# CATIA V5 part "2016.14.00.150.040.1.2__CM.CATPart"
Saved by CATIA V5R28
Part number: 2016.14.00.150.040.1.2__CM
Property "id_number": "2016.14.00.150.040.1.2"
Publications: "Absolute Axis System", "driver", "slider", "base", "cam diagram"
Bounding box of the stored display mesh (mm): x -40 to 190, y -130 to 130, z 0 to 260
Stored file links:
  N:\B2\Normteile\K\2016\11-14\015\cm\2016.14.00.150.040.1.2__CM.CATPart
  H:\CAD_Startmodelle\Tests\fill-in_PRT-SL_TEMPLATE.xlsx
  H:\CAD_Startmodelle\V5-R24\R24_TEMPLATE_PRT_FIBRO_CAM_TECNOLOGIES_INDEX.xlsx
  H:\z_Einordnen\170511__Anfrage_TK_HN\170511__CC01_TKHN.CATPart
  N:\B2\Normteile\K\2016\9xxx\2016.9024.1705.001\Entwurf_\170511__CC01_TKHN.CATPart
  N:\B2\Normteile\K\2016\9xxx\2016.9024.1707.006\Konstruktion\2016.9024.1707.006__HP__CUSTOMIZED_CAM_CM.CATPart
  N:\B2\Normteile\K\2016\9xxx\2016.9024.1707.005\Konstruktion\2016.9024.1707.005__HP__CUSTOMIZED_CAM_CM.CATPart
  N:\B2\Normteile\K\2016\9xxx\2016.9024.1707.008\Konstruktion\2016.9024.1707.008__HP__CUSTOMIZED_CAM_CM.CATPart
  N:\B2\Normteile\K\2016\9xxx\2016.9024.1707.009\Konstruktion\2016.9024.1707.009__HP__CUSTOMIZED_CAM_CM.CATPart
  N:\B2\Normteile\K\2016\9xxx\2016.9024.1707.010\Konstruktion\2016.9024.1707.010__HP__CUSTOMIZED_CAM_CM.CATPart
  N:\B2\Normteile\K\2016\9xxx\2016.9024.1708.002\Konstruktion\2016.9024.1708.002__HP__CUSTOMIZED_CAM_CM.CATPart
  N:\B2\Normteile\K\2016\9xxx\2016.9024.1802.001\Konstruktion\2016.9024.1802.001__HP__CUSTOMIZED_CAM_CM.CATPart
  N:\B2\Normteile\K\2016\9xxx\2016.9024.1802.002\Konstruktion\2016.9024.1802.002__HP__CUSTOMIZED_CAM_CM.CATPart
  N:\B2\Normteile\K\2016\9xxx\2016.9024.1811.003\Konstruktion\2016.9024.1811.003__HP__CUSTOMIZED_CAM_CM.CATPart
  N:\B2\Normteile\K\2016\9xxx\2016.9015.1811.001\Konstruktion\am\2016.9015.1811.001__AM__FCC_HV_DMC_0125-00.CATPart
  N:\B2\Normteile\K\2016\9xxx\2016.9024.1811.009\Konstruktion\2016.9024.1811.009__HP__CUSTOMIZED_CAM_CM.CATPart
  N:\B2\Normteile\K\2016\9xxx\2016.9024.1911.002\Konstruktion\am\2016.9024.1911.002__AM__CUSTOMIZED_CAM_CM.CATPart
  N:\B2\Normteile\K\2016\9xxx\2016.9024.2002.006\Konstruktion\2016.9024.2002.006__AM.CATPart
  N:\B2\Normteile\K\2016\9xxx\2016.9024.2004.001\Konstruktion\2016.9024.2004.001__AM__FCC_HV_CAEC_0260-45.CATPart
  N:\B2\Normteile\K\2016\9xxx\2016.9024.2006.002\Konstruktion\2016.9024.2006.002__AM__FCC_HV_CAEC_0260-40.CATPart
  N:\B2\Normteile\K\2016\9xxx\2016.9024.2006.005\Konstruktion\am\2016.9024.2006.005__AM__CFCC_HV_AEPC_0080-65.CATPart
  N:\B2\Normteile\K\2016\9xxx\2016.9024.2006.004\Konstruktion\am\2016.9024.2006.004__AM__CFCC_HV_AEC_0210-35.CATPart
  N:\B2\Normteile\K\2016\9xxx\2016.9026.2006.001\Konstruktion\am\2016.9026.2006.001__AM__FCC_LV_CAEC_0180-40.CATPart
  N:\B2\Normteile\K\2016\9xxx\2016.9015.2007.001\Konstruktion\am\2016.9015.2007.001__AM__FCC_HV_CDMPC_0090-00.CATPart
  N:\B2\Normteile\K\2016\9xxx\2016.9024.2005.001\Konstruktion\am\2016.9024.2005.001__AM__CFCC_HV_AEPC_1400-70.CATPart
  N:\B2\Normteile\K\2016\9xxx\2016.9024.2007.004\Konstruktion\am\2016.9024.2007.004__AM__CFCC_HV_AEC_1250-80.CATPart
  N:\B2\Normteile\K\2016\11-14\005\2016.11.00.052.040.1.02__AS__DIE_MOUNT_CAM__W52_A0_S40.CATProduct
  N:\B2\Normteile\K\2016\11-14\015\2016.11.00.150.060.1.02__AS__DIE_MOUNT_CAM__W150_A0_S60.CATProduct
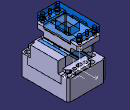
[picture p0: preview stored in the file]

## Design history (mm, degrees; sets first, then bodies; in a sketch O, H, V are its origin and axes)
Parameters
  group "process_parameters"
    modeltype = ""
    stocklist = ""
    id_number = "2016.14.00.150.040.1.2"
    id_number_rough_part = ""
    revision_index = ""
    revision_date = ""
    revision_description = ""
    category = ""
    material = ""
    manufacturing_information = ""
    standard = ""
  group "release_parameters_startmodel"
    sm_revision_index = "2016_00" {design table}
    sm_revision_date = "20.08.2016" {design table}
    sm_revision_name = "Meyer" {design table}
    sm_revision_description = "new part template FIBRO cam tecnologies" {design table}
AxisSystem1: origin (0, 0, 0), X (1, 0, 0), Y (0, 1, 0), Z (0, 0, 1)
Set1 "reference elements"
  Sketch1 "cam diagram" on ZX plane of AxisSystem1, origin (0, 0, 0), H (-1, 0, 0), V (0, 0, 1)
    line L1 (0, 0) -> (40, 0)
    line L2 (40, 0) -> (0, 40)
    point P2 (0, 40)
    line L3 (0, 40) -> (0, 0)
    length L1 = 40
    angle H L2 = 45
    horizontal: L1 H
    coincidence: P2 V
    vertical: L3 V
Body1 "finished_part" (main body)
  Body2 "rough_part"
  Add1 "rough_part": tool Body2
  Body3 "milling operations"
  Remove1 "milling operations": tool Body3
  Body4 "drilling operations"
  Remove2 "drilling operations": tool Body4
Body5 "driver"
  Solid1: solid without history
Body6 "slider"
  Solid2: solid without history
Body7 "base"
  Solid3: solid without history
Body8 "opened position"
  Body9 "slider"
    Body10 "slider"
      Solid4: linked copy from another document
    Assemble1: tool Body10
    Translate1: FirstPoint vertex [element of Sketch1 | element of Sketch1], SecondPoint vertex [element of Sketch1 | element of Sketch1], ToTransfor Assemble1
  Assemble2: tool Body9
  Body11 "driver"
    Body12 "driver"
      Solid5: linked copy from another document
    Assemble3: tool Body12
    Translate2: FirstPoint vertex [element of Sketch1 | element of Sketch1], SecondPoint vertex [element of Sketch1 | element of Sketch1], ToTransfor Assemble3
  Assemble4: tool Body11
